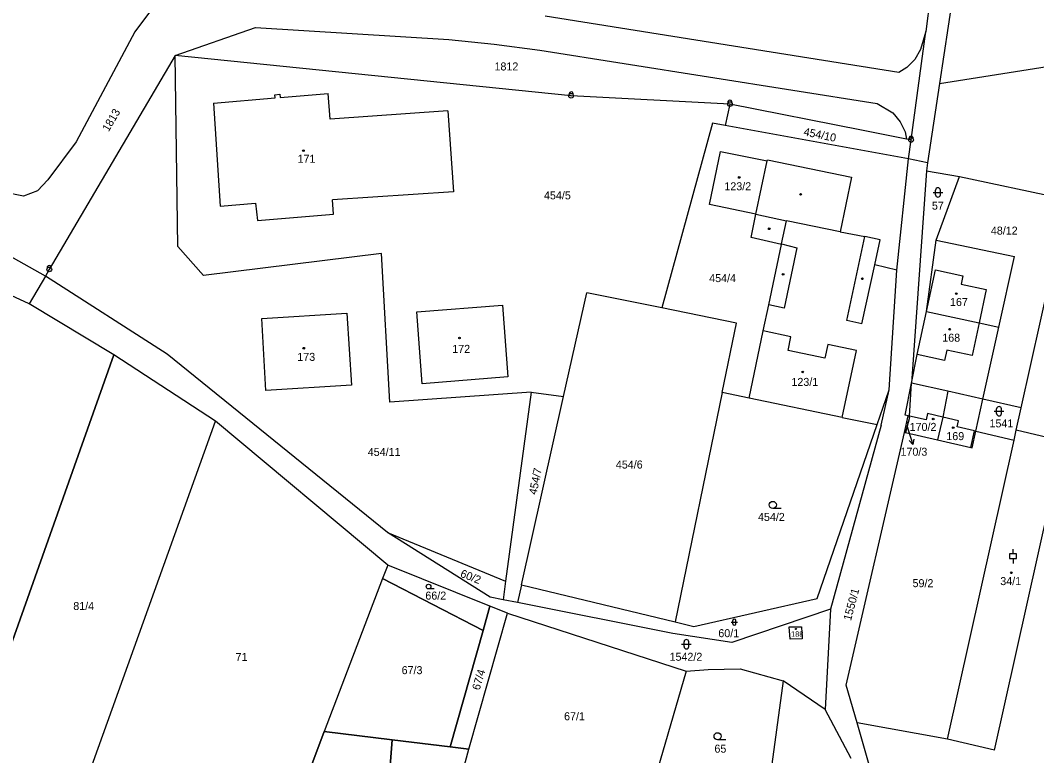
# Model space of a CAD drawing. Extents: x -801826 to -800592, y -1032871 to -1031813.
# Drawn here: x -801458.2 to -801242.3, y -1032206.7 to -1032050.6 of the extents above; entities that cross this region are included whole.
import ezdxf

# ---------------------------------------------------------------- set-up
doc = ezdxf.new("R2010")
doc.units = 0
for name, color, linetype in [('Vrstva 1', 7, 'Continuous'), ('Vrstva 16', 7, 'Continuous'), ('Vrstva 18', 7, 'Continuous'), ('Vrstva 19', 7, 'Continuous'), ('Vrstva 24', 7, 'Continuous'), ('Vrstva 25', 7, 'Continuous'), ('Vrstva 4', 7, 'Continuous')]:
    doc.layers.add(name, color=color, linetype=linetype)

msp = doc.modelspace()

# ---------------------------------------------------------------- linework, layer by layer
at = {"layer": 'Vrstva 1'}
for p, q in [((-801262.09, -1032022.19), (-801265.89, -1032052.97)), ((-801257, -1032023.94), (-801262.98, -1032064)), ((-801430.52, -1032048.58), (-801433.82, -1032053.02)), ((-801271.58, -1032061.66), (-801346.73, -1032049.72)), ((-801433.82, -1032053.02), (-801446.28, -1032076.38)), ((-801425.29, -1032058.05), (-801408.2, -1032052.09)), ((-801408.2, -1032052.09), (-801367.19, -1032054.68)), ((-801269.02, -1032075.99), (-801265.89, -1032052.97)), ((-801265.89, -1032052.97), (-801267.03, -1032056.81)), ((-801367.19, -1032054.68), (-801357.51, -1032055.63)), ((-801357.51, -1032055.63), (-801347.87, -1032056.96)), ((-801347.87, -1032056.96), (-801276.24, -1032068.26)), ((-801267.03, -1032056.81), (-801268.24, -1032058.88)), ((-801425.29, -1032058.05), (-801452, -1032103.48)), ((-801341.2, -1032066.62), (-801425.29, -1032058.05)), ((-801424.71, -1032098.65), (-801425.29, -1032058.05)), ((-801268.24, -1032058.88), (-801269.9, -1032060.6)), ((-801262.98, -1032064), (-801231.11, -1032058.94)), ((-801269.9, -1032060.6), (-801271.58, -1032061.66)), ((-801262.98, -1032064), (-801265.5, -1032080.86)), ((-801403, -1032066.99), (-801392.82, -1032066.14)), ((-801392.37, -1032071.55), (-801392.82, -1032066.14)), ((-801417.15, -1032068.18), (-801404.07, -1032067.08)), ((-801417.15, -1032068.18), (-801415.71, -1032090.06)), ((-801404.13, -1032066.39), (-801403.06, -1032066.3)), ((-801404.07, -1032067.08), (-801404.13, -1032066.39)), ((-801403.06, -1032066.3), (-801403, -1032066.99)), ((-801307.47, -1032068.37), (-801341.2, -1032066.62)), ((-801307.47, -1032068.37), (-801308.47, -1032072.93)), ((-801279.56, -1032073.9), (-801307.47, -1032068.37)), ((-801276.24, -1032068.26), (-801272.9, -1032070.27)), ((-801367.35, -1032069.84), (-801392.37, -1032071.55)), ((-801367.35, -1032069.84), (-801366.2, -1032086.98)), ((-801272.9, -1032070.27), (-801271.36, -1032072.12)), ((-801311.17, -1032072.43), (-801321.92, -1032111.67)), ((-801308.47, -1032072.93), (-801311.17, -1032072.43)), ((-801271.36, -1032072.12), (-801270.3, -1032074.27)), ((-801269.59, -1032080.03), (-801308.47, -1032072.93)), ((-801269.97, -1032075.8), (-801279.56, -1032073.9)), ((-801270.3, -1032074.27), (-801269.97, -1032075.8)), ((-801446.28, -1032076.38), (-801452.29, -1032084.49)), ((-801269.02, -1032075.99), (-801269.97, -1032075.8)), ((-801269.59, -1032080.03), (-801269.02, -1032075.99)), ((-801311.85, -1032089.67), (-801309.47, -1032078.43)), ((-801309.47, -1032078.43), (-801299.58, -1032080.44)), ((-801301.96, -1032091.78), (-801299.58, -1032080.44)), ((-801299.58, -1032080.44), (-801299.53, -1032080.2)), ((-801299.53, -1032080.2), (-801281.65, -1032083.9)), ((-801272.06, -1032103.62), (-801269.59, -1032080.03)), ((-801265.5, -1032080.86), (-801269.59, -1032080.03)), ((-801265.5, -1032080.86), (-801265.75, -1032082.53)), ((-801265.75, -1032082.53), (-801268.91, -1032127.61)), ((-801265.75, -1032082.53), (-801258.71, -1032083.73)), ((-801452.29, -1032084.49), (-801454.49, -1032086.8)), ((-801281.65, -1032083.9), (-801284.05, -1032095.51)), ((-801263.66, -1032097.24), (-801258.71, -1032083.73)), ((-801258.71, -1032083.73), (-801235.82, -1032088.67)), ((-801457.47, -1032087.94), (-801461.63, -1032087.11)), ((-801454.49, -1032086.8), (-801457.47, -1032087.94)), ((-801366.2, -1032086.98), (-801391.87, -1032088.72)), ((-801415.71, -1032090.06), (-801408.25, -1032089.43)), ((-801408.25, -1032089.43), (-801407.8, -1032093.1)), ((-801391.69, -1032091.74), (-801391.87, -1032088.72)), ((-801301.96, -1032091.78), (-801311.85, -1032089.67)), ((-801245.62, -1032132.9), (-801235.82, -1032088.67)), ((-801407.8, -1032093.1), (-801391.69, -1032091.74)), ((-801303, -1032096.7), (-801301.96, -1032091.78)), ((-801452.83, -1032104.89), (-801474.57, -1032092.78)), ((-801284.05, -1032095.51), (-801278.83, -1032096.52)), ((-801296.54, -1032098.22), (-801303, -1032096.7)), ((-801299.24, -1032111.01), (-801296.54, -1032098.22)), ((-801275.6, -1032097.21), (-801278.83, -1032096.52)), ((-801276.72, -1032102.48), (-801275.6, -1032097.21)), ((-801265.72, -1032112.42), (-801263.66, -1032097.24)), ((-801263.66, -1032097.24), (-801247.02, -1032100.74)), ((-801419.27, -1032104.78), (-801424.71, -1032098.65)), ((-801381.45, -1032100.13), (-801419.27, -1032104.78)), ((-801379.71, -1032131.67), (-801381.45, -1032100.13)), ((-801250.36, -1032115.72), (-801247.02, -1032100.74)), ((-801272.06, -1032103.62), (-801276.72, -1032102.48)), ((-801456.3, -1032110.81), (-801470.82, -1032104.06)), ((-801452.83, -1032104.89), (-801456.3, -1032110.81)), ((-801452, -1032103.48), (-801452.83, -1032104.89)), ((-801426.98, -1032121.5), (-801452.83, -1032104.89)), ((-801273.68, -1032129.04), (-801272.06, -1032103.62)), ((-801342.82, -1032130.49), (-801337.89, -1032108.42)), ((-801321.92, -1032111.67), (-801337.89, -1032108.42)), ((-801438.33, -1032121.65), (-801456.3, -1032110.81)), ((-801373.96, -1032112.47), (-801355.78, -1032111.06)), ((-801355.78, -1032111.06), (-801354.64, -1032126.28)), ((-801300.41, -1032116.55), (-801299.24, -1032111.01)), ((-801406.89, -1032113.92), (-801388.81, -1032112.77)), ((-801388.81, -1032112.77), (-801387.84, -1032128.05)), ((-801372.83, -1032127.8), (-801373.96, -1032112.47)), ((-801306.09, -1032114.89), (-801321.92, -1032111.67)), ((-801267.7, -1032121.56), (-801265.72, -1032112.42)), ((-801265.72, -1032112.42), (-801254.57, -1032114.83)), ((-801406.02, -1032129.21), (-801406.89, -1032113.92)), ((-801309.1, -1032129.65), (-801306.09, -1032114.89)), ((-801254.57, -1032114.83), (-801250.36, -1032115.72)), ((-801253.77, -1032131.05), (-801250.36, -1032115.72)), ((-801303.42, -1032130.83), (-801300.41, -1032116.55)), ((-801460.58, -1032184.52), (-801438.33, -1032121.65)), ((-801438.33, -1032121.65), (-801460.58, -1032184.52)), ((-801416.74, -1032135.73), (-801438.33, -1032121.65)), ((-801416.74, -1032135.73), (-801438.33, -1032121.65)), ((-801380.16, -1032159.36), (-801426.98, -1032121.5)), ((-801268.91, -1032127.61), (-801267.7, -1032121.56)), ((-801354.64, -1032126.28), (-801372.83, -1032127.8)), ((-801387.84, -1032128.05), (-801406.02, -1032129.21)), ((-801270.28, -1032134.44), (-801268.91, -1032127.61)), ((-801269.36, -1032134.64), (-801268.91, -1032127.61)), ((-801261.19, -1032129.36), (-801268.91, -1032127.61)), ((-801349.66, -1032129.57), (-801379.71, -1032131.67)), ((-801349.66, -1032129.57), (-801355.11, -1032169.64)), ((-801351.73, -1032170.46), (-801342.82, -1032130.49)), ((-801349.66, -1032129.57), (-801342.82, -1032130.49)), ((-801309.1, -1032129.65), (-801319.13, -1032178.33)), ((-801303.42, -1032130.83), (-801309.1, -1032129.65)), ((-801283.65, -1032134.95), (-801303.42, -1032130.83)), ((-801276.23, -1032136.41), (-801273.68, -1032129.04)), ((-801275.4, -1032136.57), (-801273.68, -1032129.04)), ((-801261.19, -1032129.36), (-801262.27, -1032134.83)), ((-801253.77, -1032131.05), (-801261.19, -1032129.36)), ((-801255.28, -1032137.84), (-801253.77, -1032131.05)), ((-801245.62, -1032132.9), (-801253.77, -1032131.05)), ((-801246.67, -1032137.64), (-801245.62, -1032132.9)), ((-801283.65, -1032134.95), (-801276.23, -1032136.41)), ((-801270.39, -1032138.1), (-801269.6, -1032134.59)), ((-801269.6, -1032134.59), (-801270.28, -1032134.44)), ((-801269.38, -1032134.93), (-801270.2, -1032138.14)), ((-801269.38, -1032134.93), (-801269.36, -1032134.64)), ((-801262.27, -1032134.83), (-801263.37, -1032139.69)), ((-801448.05, -1032222.93), (-801416.74, -1032135.73)), ((-801448.05, -1032222.93), (-801416.74, -1032135.73)), ((-801380.15, -1032166.29), (-801416.74, -1032135.73)), ((-801288.99, -1032173.33), (-801276.23, -1032136.41)), ((-801275.4, -1032136.57), (-801286.12, -1032175.6)), ((-801282.81, -1032191.78), (-801270.39, -1032138.1)), ((-801270.39, -1032138.1), (-801270.2, -1032138.14)), ((-801270.2, -1032138.14), (-801263.37, -1032139.69)), ((-801256.06, -1032141.35), (-801255.28, -1032137.84)), ((-801255.28, -1032137.84), (-801247.14, -1032139.77)), ((-801247.14, -1032139.77), (-801246.67, -1032137.64)), ((-801236.7, -1032139.95), (-801246.67, -1032137.64)), ((-801263.37, -1032139.69), (-801256.35, -1032141.28)), ((-801261.28, -1032203.24), (-801247.14, -1032139.77)), ((-801256.35, -1032141.28), (-801256.06, -1032141.35)), ((-801358.41, -1032173.07), (-801380.16, -1032159.36)), ((-801380.16, -1032159.36), (-801355.11, -1032169.64)), ((-801380.15, -1032166.29), (-801381.22, -1032169.08)), ((-801380.15, -1032166.29), (-801381.22, -1032169.08)), ((-801358.43, -1032175.01), (-801380.15, -1032166.29)), ((-801358.43, -1032175.01), (-801380.15, -1032166.29)), ((-801381.22, -1032169.08), (-801393.66, -1032201.6)), ((-801381.22, -1032169.08), (-801393.66, -1032201.6)), ((-801359.89, -1032180.17), (-801381.22, -1032169.08)), ((-801381.22, -1032169.08), (-801359.89, -1032180.17)), ((-801359.89, -1032180.17), (-801381.22, -1032169.08)), ((-801355.11, -1032169.64), (-801355.65, -1032173.62)), ((-801351.73, -1032170.46), (-801352.57, -1032174.23)), ((-801351.73, -1032170.46), (-801319.13, -1032178.33)), ((-801355.65, -1032173.62), (-801358.41, -1032173.07)), ((-801352.57, -1032174.23), (-801355.65, -1032173.62)), ((-801315.17, -1032179.29), (-801288.99, -1032173.33)), ((-801359.89, -1032180.17), (-801358.43, -1032175.01)), ((-801359.89, -1032180.17), (-801358.43, -1032175.01)), ((-801358.43, -1032175.01), (-801359.89, -1032180.17)), ((-801354.73, -1032176.5), (-801358.43, -1032175.01)), ((-801354.73, -1032176.5), (-801358.43, -1032175.01)), ((-801319.63, -1032180.77), (-801352.57, -1032174.23)), ((-801286.12, -1032175.6), (-801307.04, -1032182.72)), ((-801286.12, -1032175.6), (-801287.23, -1032196.91)), ((-801362.89, -1032205.37), (-801354.73, -1032176.5)), ((-801362.89, -1032205.37), (-801354.73, -1032176.5)), ((-801354.73, -1032176.5), (-801316.77, -1032188.79)), ((-801319.13, -1032178.33), (-801315.17, -1032179.29)), ((-801366.89, -1032204.88), (-801359.89, -1032180.17)), ((-801366.89, -1032204.88), (-801359.89, -1032180.17)), ((-801359.89, -1032180.17), (-801366.89, -1032204.88)), ((-801294.88, -1032179.39), (-801292.29, -1032179.35)), ((-801294.72, -1032181.99), (-801294.88, -1032179.39)), ((-801292.29, -1032179.35), (-801292.13, -1032181.9)), ((-801307.04, -1032182.72), (-801319.63, -1032180.77)), ((-801292.13, -1032181.9), (-801294.72, -1032181.99)), ((-801316.77, -1032188.79), (-801323.85, -1032212.97)), ((-801316.77, -1032188.79), (-801312.1, -1032188.42)), ((-801312.1, -1032188.42), (-801305.34, -1032188.3)), ((-801305.34, -1032188.3), (-801296.17, -1032190.86)), ((-801296.17, -1032190.86), (-801300.07, -1032219.68)), ((-801287.23, -1032196.91), (-801296.17, -1032190.86)), ((-801280.45, -1032199.73), (-801282.81, -1032191.78)), ((-801281.75, -1032207.34), (-801287.23, -1032196.91)), ((-801261.28, -1032203.24), (-801280.45, -1032199.73)), ((-801276.11, -1032214.97), (-801280.45, -1032199.73)), ((-801396.23, -1032208.59), (-801393.66, -1032201.6)), ((-801393.66, -1032201.6), (-801396.23, -1032208.59)), ((-801393.66, -1032201.6), (-801379.18, -1032203.38)), ((-801379.18, -1032203.38), (-801393.66, -1032201.6)), ((-801393.66, -1032201.6), (-801379.18, -1032203.38)), ((-801381.98, -1032239.7), (-801379.18, -1032203.38)), ((-801381.98, -1032239.7), (-801379.18, -1032203.38)), ((-801379.18, -1032203.38), (-801381.98, -1032239.7)), ((-801366.89, -1032204.88), (-801379.18, -1032203.38)), ((-801379.18, -1032203.38), (-801366.89, -1032204.88)), ((-801366.89, -1032204.88), (-801379.18, -1032203.38)), ((-801362.89, -1032205.37), (-801366.89, -1032204.88)), ((-801366.89, -1032204.88), (-801362.89, -1032205.37)), ((-801362.89, -1032205.37), (-801366.89, -1032204.88)), ((-801365.14, -1032213.36), (-801362.89, -1032205.37)), ((-801365.14, -1032213.36), (-801362.89, -1032205.37))]:
    msp.add_line(p, q, dxfattribs=at)
at = {"layer": 'Vrstva 16'}
for p, q in [((-801269.94, -1032136.61), (-801269.55, -1032137.78)), ((-801269.55, -1032137.78), (-801268.61, -1032140.63))]:
    msp.add_line(p, q, dxfattribs=at)
msp.add_lwpolyline([(-801268.45, -1032139.52), (-801268.61, -1032140.63), (-801269.4, -1032139.84)], dxfattribs=at)
at = {"layer": 'Vrstva 24'}
for centre, radius in [((-801341.2, -1032066.62), 0.5), ((-801341.2, -1032066.62), 0.0364), ((-801307.47, -1032068.37), 0.5), ((-801307.47, -1032068.37), 0.0364), ((-801269.02, -1032075.99), 0.5), ((-801269.02, -1032075.99), 0.0364), ((-801452, -1032103.48), 0.5), ((-801452, -1032103.48), 0.0364)]:
    msp.add_circle(centre, radius, dxfattribs=at)
for centre in [(-801341.2, -1032066.25), (-801307.47, -1032068), (-801269.02, -1032075.62), (-801452, -1032103.11)]:
    msp.add_arc(centre, 0.45, 344.4473, 196.3778, dxfattribs=at)
at = {"layer": 'Vrstva 25'}
for p, q in [((-801264.3, -1032087.13), (-801262.3, -1032087.13)), ((-801263.8, -1032087.63), (-801263.8, -1032086.63)), ((-801262.8, -1032087.63), (-801262.8, -1032086.63)), ((-801250.84, -1032134.09), (-801250.84, -1032133.09)), ((-801249.84, -1032134.09), (-801249.84, -1032133.09)), ((-801251.34, -1032133.59), (-801249.34, -1032133.59)), ((-801296.62, -1032154.23), (-801298.37, -1032154.23)), ((-801247.35, -1032163.89), (-801247.35, -1032162.89)), ((-801247.35, -1032164.89), (-801247.35, -1032165.89)), ((-801370.31, -1032171.33), (-801371.48, -1032171.33)), ((-801307.21, -1032178.38), (-801305.87, -1032178.38)), ((-801306.88, -1032178.71), (-801306.88, -1032178.05)), ((-801306.21, -1032178.71), (-801306.21, -1032178.05)), ((-801317.23, -1032183.56), (-801317.23, -1032182.56)), ((-801316.23, -1032183.56), (-801316.23, -1032182.56)), ((-801317.73, -1032183.06), (-801315.73, -1032183.06)), ((-801308.35, -1032203.35), (-801310.1, -1032203.35))]:
    msp.add_line(p, q, dxfattribs=at)
msp.add_lwpolyline([(-801248.1, -1032164.89), (-801246.6, -1032164.89), (-801246.6, -1032163.89), (-801248.1, -1032163.89)], close=True, dxfattribs=at)
for centre, radius in [((-801398.03, -1032078.27), 0.175), ((-801305.5, -1032083.95), 0.175), ((-801292.46, -1032087.55), 0.175), ((-801299.13, -1032094.86), 0.175), ((-801296.19, -1032104.54), 0.175), ((-801279.35, -1032105.47), 0.175), ((-801259.41, -1032108.63), 0.175), ((-801364.9, -1032118.06), 0.175), ((-801260.81, -1032116.18), 0.175), ((-801397.96, -1032120.21), 0.175), ((-801292.03, -1032125.26), 0.175), ((-801264.31, -1032135.25), 0.175), ((-801269.78, -1032135.99), 0.117), ((-801260.07, -1032137.1), 0.175), ((-801298.37, -1032153.48), 0.75), ((-801247.73, -1032167.9), 0.175), ((-801371.48, -1032170.83), 0.503), ((-801293.47, -1032179.83), 0.117), ((-801310.1, -1032202.6), 0.75)]:
    msp.add_circle(centre, radius, dxfattribs=at)
for centre, radius, start, end in [((-801263.3, -1032086.63), 0.5, 0, 180), ((-801263.3, -1032087.63), 0.5, 180, 0), ((-801250.34, -1032133.09), 0.5, 0, 180), ((-801250.34, -1032134.09), 0.5, 180, 0), ((-801306.54, -1032178.05), 0.335, 0, 180), ((-801306.54, -1032178.71), 0.335, 180, 0), ((-801316.73, -1032182.56), 0.5, 0, 180), ((-801316.73, -1032183.56), 0.5, 180, 0)]:
    msp.add_arc(centre, radius, start, end, dxfattribs=at)
at = {"layer": 'Vrstva 4'}
for p, q in [((-801301.96, -1032091.78), (-801295.47, -1032093.15)), ((-801296.51, -1032098.07), (-801295.47, -1032093.15)), ((-801284.05, -1032095.51), (-801295.47, -1032093.15)), ((-801296.54, -1032098.22), (-801296.51, -1032098.07)), ((-801296.51, -1032098.07), (-801293.29, -1032098.9)), ((-801282.67, -1032114.31), (-801278.83, -1032096.52)), ((-801293.29, -1032098.9), (-801295.99, -1032111.7)), ((-801279.44, -1032115.01), (-801276.72, -1032102.48)), ((-801265.72, -1032112.42), (-801263.81, -1032103.59)), ((-801263.81, -1032103.59), (-801257.99, -1032104.85)), ((-801257.99, -1032104.85), (-801258.37, -1032106.61)), ((-801258.37, -1032106.61), (-801253.04, -1032107.76)), ((-801253.04, -1032107.76), (-801254.57, -1032114.83)), ((-801295.99, -1032111.7), (-801299.24, -1032111.01)), ((-801279.44, -1032115.01), (-801282.67, -1032114.31)), ((-801254.57, -1032114.83), (-801256.07, -1032121.76)), ((-801294.53, -1032117.78), (-801300.41, -1032116.55)), ((-801295.14, -1032120.72), (-801294.53, -1032117.78)), ((-801286.69, -1032119.41), (-801287.3, -1032122.35)), ((-801280.61, -1032120.68), (-801286.69, -1032119.41)), ((-801287.3, -1032122.35), (-801295.14, -1032120.72)), ((-801283.65, -1032134.95), (-801280.61, -1032120.68)), ((-801261.91, -1032122.81), (-801267.7, -1032121.56)), ((-801261.44, -1032120.6), (-801261.91, -1032122.81)), ((-801256.07, -1032121.76), (-801261.44, -1032120.6)), ((-801269.36, -1032134.64), (-801269.6, -1032134.59)), ((-801265.82, -1032135.45), (-801269.36, -1032134.64)), ((-801265.52, -1032134.11), (-801265.82, -1032135.45)), ((-801262.27, -1032134.83), (-801265.52, -1032134.11)), ((-801258.95, -1032135.64), (-801262.27, -1032134.83)), ((-801259.24, -1032136.94), (-801258.95, -1032135.64)), ((-801255.56, -1032137.77), (-801259.24, -1032136.94)), ((-801256.35, -1032141.28), (-801255.56, -1032137.77)), ((-801251.33, -1032205.54), (-801236.7, -1032139.95)), ((-801251.33, -1032205.54), (-801261.28, -1032203.24))]:
    msp.add_line(p, q, dxfattribs=at)

# ---------------------------------------------------------------- texts
at = {"layer": 'Vrstva 16'}
msp.add_text('170/3', height=1.7, dxfattribs=at).set_placement((-801271.26, -1032143.04))
at = {"layer": 'Vrstva 18'}
for s, p in [('1812', (-801357.47, -1032061.24)), ('454/5', (-801346.96, -1032088.61)), ('57', (-801264.59, -1032090.79)), ('48/12', (-801252.07, -1032096.09)), ('454/4', (-801311.88, -1032106.18)), ('1541', (-801252.36, -1032137.02)), ('454/11', (-801384.38, -1032143.09)), ('454/6', (-801331.7, -1032145.76)), ('454/2', (-801301.52, -1032156.89)), ('59/2', (-801268.7, -1032170.95)), ('66/2', (-801372.15, -1032173.59)), ('81/4', (-801446.91, -1032175.8)), ('60/1', (-801309.94, -1032181.57)), ('71', (-801412.45, -1032186.62)), ('1542/2', (-801320.3, -1032186.58)), ('67/3', (-801377.19, -1032189.42)), ('67/1', (-801342.7, -1032199.21)), ('65', (-801310.77, -1032206.09))]:
    msp.add_text(s, height=1.7, dxfattribs=at).set_placement(p)
for s, rotation, p in [('1813', 59.5303, (-801439.41, -1032074.37)), ('454/10', 348.38, (-801291.94, -1032075.01)), ('454/7', 78.4952, (-801348.54, -1032151.41)), ('60/2', 338.5977, (-801364.88, -1032168.7)), ('1550/1', 75.1339, (-801281.78, -1032178.18)), ('67/4', 73.347, (-801360.65, -1032192.95))]:
    msp.add_text(s, height=1.7, rotation=rotation, dxfattribs=at).set_placement(p)
at = {"layer": 'Vrstva 19'}
for s, height, p in [('171', 1.7, (-801399.29, -1032080.84)), ('123/2', 1.7, (-801308.66, -1032086.68)), ('167', 1.7, (-801260.75, -1032111.25)), ('168', 1.7, (-801262.39, -1032118.83)), ('172', 1.7, (-801366.44, -1032121.21)), ('173', 1.7, (-801399.34, -1032122.9)), ('123/1', 1.7, (-801294.42, -1032128.22)), ('170/3', 0.1, (-801270.1, -1032136.61)), ('170/2', 1.7, (-801269.32, -1032137.77)), ('169', 1.7, (-801261.53, -1032139.73)), ('34/1', 1.7, (-801250.07, -1032170.51)), ('188', 1.14, (-801294.5, -1032181.48))]:
    msp.add_text(s, height=height, dxfattribs=at).set_placement(p)

doc.saveas('drawing.dxf')
